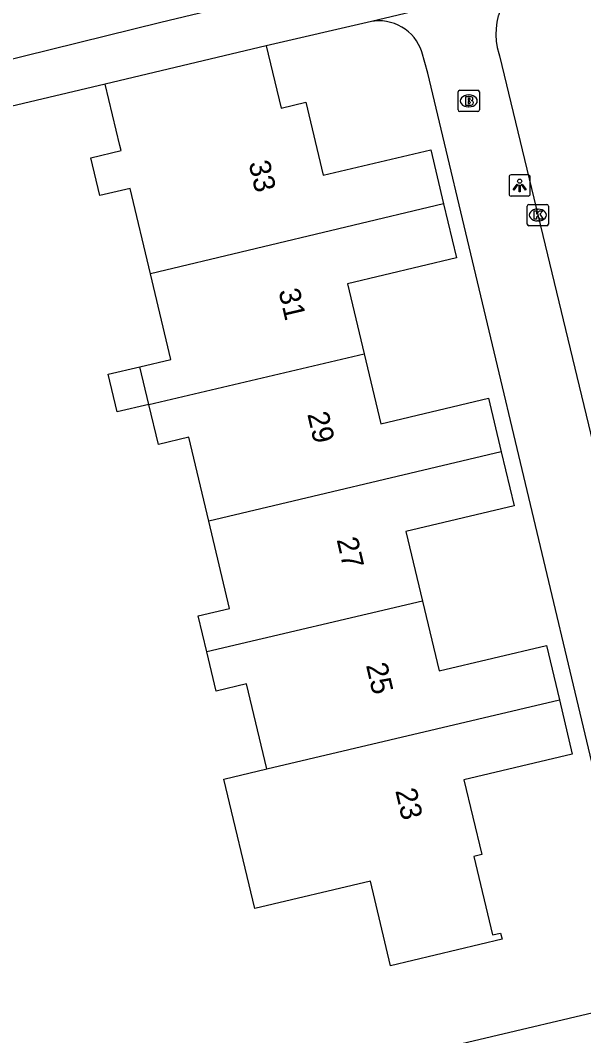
# Model space of a CAD drawing. Extents: x 158038 to 159242, y 380133 to 381214.
# Drawn here: x 158563.26 to 158589.79, y 380931.84 to 380979.68 of the extents above; entities that cross this region are included whole.
import ezdxf

# ---------------------------------------------------------------- set-up
doc = ezdxf.new("R2010")
doc.units = 0
for name, color, linetype in [('IMGEO_Brandkraan', 7, 'Continuous'), ('IMGEO_Fietspad_open', 7, 'Continuous'), ('IMGEO_Kolk', 7, 'Continuous'), ('IMGEO_Lichtpunt', 7, 'Continuous'), ('IMGEO_Pand', 7, 'Continuous'), ('IMGEO_Pand_nummerreeks', 7, 'Continuous'), ('IMGEO_Voetpad_open', 7, 'Continuous')]:
    doc.layers.add(name, color=color, linetype=linetype)

msp = doc.modelspace()

# ---------------------------------------------------------------- linework, layer by layer
at = {"layer": 'IMGEO_Brandkraan'}
for p, q in [((158583.878, 380975.455), (158583.878, 380976.307)), ((158583.953, 380976.381), (158584.805, 380976.381)), ((158584.366, 380976.161), (158584.391, 380976.161)), ((158584.879, 380976.307), (158584.879, 380975.455)), ((158584.805, 380975.381), (158583.953, 380975.381)), ((158584.389, 380975.601), (158584.364, 380975.601))]:
    msp.add_line(p, q, dxfattribs=at)
for points in [[(158583.878, 380975.455), (158583.878, 380976.307)], [(158583.953, 380976.381), (158584.805, 380976.381)], [(158584.879, 380976.307), (158584.879, 380975.455)], [(158584.226, 380976.081), (158584.226, 380975.681), (158584.439, 380975.681)], [(158584.457, 380976.081), (158584.226, 380976.081)], [(158584.405, 380976), (158584.351, 380976), (158584.351, 380975.924)], [(158584.351, 380975.924), (158584.404, 380975.924)], [(158584.413, 380975.848), (158584.351, 380975.848), (158584.351, 380975.767)], [(158584.351, 380975.767), (158584.413, 380975.767)], [(158584.805, 380975.381), (158583.953, 380975.381)]]:
    msp.add_lwpolyline(points, dxfattribs=at)
for centre, radius, start, end in [((158583.955, 380976.305), 0.0765, 91.552, 178.448), ((158583.955, 380976.305), 0.0765, 91.552, 178.448), ((158584.803, 380976.305), 0.0765, 1.552, 88.448), ((158584.803, 380976.305), 0.0765, 1.552, 88.448), ((158584.406, 380975.962), 0.0379, 267.8285, 90.9355), ((158584.414, 380975.807), 0.0404, 269.8759, 90.5077), ((158584.445, 380975.932), 0.251, 268.6676, 293.5347), ((158584.461, 380975.936), 0.145, 59.4692, 91.5367), ((158584.486, 380975.983), 0.0922, 285.5137, 58.1501), ((158584.491, 380975.791), 0.105, 301.3115, 78.989), ((158583.955, 380975.457), 0.0765, 181.552, 268.448), ((158583.955, 380975.457), 0.0765, 181.552, 268.448), ((158584.803, 380975.457), 0.0765, 271.552, 358.448), ((158584.803, 380975.457), 0.0765, 271.552, 358.448)]:
    msp.add_arc(centre, radius, start, end, dxfattribs=at)
for centre, major_axis, ratio, start_param, end_param in [((158584.365, 380975.881), (-0.387, 0.002), 0.722429, 4.712389, 7.853982), ((158584.39, 380975.881), (-0.39, 0.002), 0.717154, 1.570796, 4.712389)]:
    msp.add_ellipse(centre, major_axis=major_axis, ratio=ratio, start_param=start_param, end_param=end_param, dxfattribs=at)
at = {"layer": 'IMGEO_Fietspad_open'}
msp.add_lwpolyline([(158543.487, 380975.057), (158559.5, 380977.024), (158569.881, 380979.588), (158585.768, 380983.41), (158590.087, 380984.449), (158613.803, 380989.844), (158626.388, 380992.815), (158628.561, 380993.352), (158629.543, 380993.657), (158646.352, 380999.546)], dxfattribs=at)
at = {"layer": 'IMGEO_Kolk'}
for p, q in [((158587.13, 380970.077), (158587.13, 380970.929)), ((158587.205, 380971.003), (158588.057, 380971.003)), ((158588.131, 380970.929), (158588.131, 380970.077)), ((158587.618, 380970.783), (158587.643, 380970.783)), ((158588.057, 380970.003), (158587.205, 380970.003)), ((158587.641, 380970.223), (158587.616, 380970.223))]:
    msp.add_line(p, q, dxfattribs=at)
for points in [[(158587.13, 380970.077), (158587.13, 380970.929)], [(158587.205, 380971.003), (158588.057, 380971.003)], [(158588.131, 380970.929), (158588.131, 380970.077)], [(158587.451, 380970.703), (158587.574, 380970.703), (158587.574, 380970.552), (158587.704, 380970.703), (158587.868, 380970.703), (158587.722, 380970.552), (158587.875, 380970.303), (158587.723, 380970.303), (158587.638, 380970.467), (158587.574, 380970.4), (158587.574, 380970.303), (158587.451, 380970.303), (158587.451, 380970.703)], [(158588.057, 380970.003), (158587.205, 380970.003)]]:
    msp.add_lwpolyline(points, dxfattribs=at)
for centre, start, end in [((158587.207, 380970.927), 91.552, 178.448), ((158587.207, 380970.927), 91.552, 178.448), ((158588.055, 380970.927), 1.552, 88.448), ((158588.055, 380970.927), 1.552, 88.448), ((158587.207, 380970.079), 181.552, 268.448), ((158587.207, 380970.079), 181.552, 268.448), ((158588.055, 380970.079), 271.552, 358.448), ((158588.055, 380970.079), 271.552, 358.448)]:
    msp.add_arc(centre, 0.0765, start, end, dxfattribs=at)
for centre, major_axis, ratio, start_param, end_param in [((158587.617, 380970.503), (-0.387, 0.002), 0.722429, 4.712389, 7.853982), ((158587.642, 380970.503), (-0.39, 0.002), 0.717154, 1.570796, 4.712389)]:
    msp.add_ellipse(centre, major_axis=major_axis, ratio=ratio, start_param=start_param, end_param=end_param, dxfattribs=at)
at = {"layer": 'IMGEO_Lichtpunt'}
for p, q in [((158587.178, 380972.397), (158586.37, 380972.397)), ((158587.178, 380972.397), (158586.37, 380972.397)), ((158586.276, 380972.302), (158586.276, 380971.495)), ((158586.276, 380972.302), (158586.276, 380971.495)), ((158587.272, 380971.495), (158587.272, 380972.302)), ((158587.272, 380971.495), (158587.272, 380972.302)), ((158586.37, 380971.401), (158587.178, 380971.401)), ((158586.37, 380971.401), (158587.178, 380971.401))]:
    msp.add_line(p, q, dxfattribs=at)
for points in [[(158586.65, 380971.966), (158586.689, 380971.938), (158586.501, 380971.676), (158586.463, 380971.703), (158586.65, 380971.966)], [(158586.752, 380971.918), (158586.799, 380971.918), (158586.799, 380971.596), (158586.752, 380971.596), (158586.752, 380971.918)], [(158586.862, 380971.938), (158586.9, 380971.965), (158587.087, 380971.703), (158587.048, 380971.675), (158586.862, 380971.938)]]:
    msp.add_lwpolyline(points, dxfattribs=at)
msp.add_circle((158586.775, 380972.1), 0.0994, dxfattribs=at)
for centre, start, end in [((158586.37, 380972.302), 90, 180), ((158586.37, 380972.302), 90, 180), ((158587.178, 380972.302), 0, 90), ((158587.178, 380972.302), 0, 90), ((158586.37, 380971.495), 180, 270), ((158586.37, 380971.495), 180, 270), ((158587.178, 380971.495), 270, 0), ((158587.178, 380971.495), 270, 360)]:
    msp.add_arc(centre, 0.0946, start, end, dxfattribs=at)
at = {"layer": 'IMGEO_Pand'}
for points in [[(158574.841, 380978.474), (158567.252, 380976.671)], [(158574.841, 380978.474), (158575.536, 380975.545), (158576.705, 380975.818), (158577.522, 380972.378), (158582.586, 380973.583), (158583.191, 380971.038)], [(158569.385, 380967.739), (158568.429, 380971.758), (158567.007, 380971.42), (158566.584, 380973.2), (158568.005, 380973.538), (158567.949, 380973.773), (158567.252, 380976.671)], [(158583.191, 380971.038), (158569.385, 380967.739)], [(158583.191, 380971.038), (158583.797, 380968.491), (158578.665, 380967.27), (158579.452, 380963.963)], [(158568.89, 380963.356), (158570.345, 380963.702), (158569.385, 380967.739)], [(158569.313, 380961.578), (158579.452, 380963.963)], [(158579.452, 380963.963), (158580.234, 380960.673), (158585.306, 380961.879), (158585.908, 380959.349)], [(158569.313, 380961.578), (158567.813, 380961.225), (158567.391, 380962.999), (158568.89, 380963.356)], [(158569.313, 380961.578), (158568.89, 380963.356)], [(158572.131, 380956.083), (158571.19, 380960.039), (158569.76, 380959.699), (158569.313, 380961.578)], [(158585.908, 380959.349), (158572.131, 380956.083)], [(158585.908, 380959.349), (158586.514, 380956.802), (158581.42, 380955.59), (158582.201, 380952.308)], [(158572.04, 380949.918), (158571.635, 380951.62), (158573.109, 380951.97), (158572.131, 380956.083)], [(158582.201, 380952.308), (158572.04, 380949.918)], [(158582.201, 380952.308), (158582.983, 380949.021), (158588.036, 380950.223), (158588.647, 380947.654)], [(158574.868, 380944.403), (158573.914, 380948.415), (158572.478, 380948.073), (158572.04, 380949.918)], [(158588.647, 380947.654), (158589.253, 380945.105), (158584.15, 380943.891), (158584.988, 380940.367), (158584.618, 380940.279), (158585.498, 380936.582), (158585.877, 380936.672), (158585.947, 380936.381), (158580.693, 380935.131), (158579.744, 380939.12), (158574.296, 380937.823), (158572.845, 380943.926), (158574.868, 380944.403)], [(158574.868, 380944.403), (158588.647, 380947.654)]]:
    msp.add_lwpolyline(points, dxfattribs=at)
at = {"layer": 'IMGEO_Voetpad_open'}
for points in [[(158587.388, 380981.452), (158579.796, 380979.628)], [(158587.388, 380981.452), (158587.187, 380981.386), (158586.992, 380981.302), (158586.806, 380981.202), (158586.629, 380981.085), (158586.464, 380980.952), (158586.311, 380980.806), (158586.172, 380980.646), (158586.048, 380980.475), (158585.939, 380980.293), (158585.848, 380980.102), (158585.773, 380979.904), (158585.768, 380979.888), (158585.705, 380979.595), (158585.668, 380979.297), (158585.658, 380978.997), (158585.675, 380978.697), (158585.718, 380978.4), (158585.788, 380978.108), (158585.819, 380978.007), (158591.091, 380956.193)], [(158579.796, 380979.628), (158574.841, 380978.474)], [(158592.43, 380935.228), (158582.451, 380977.181), (158582.17, 380978.194), (158582.101, 380978.373), (158582.016, 380978.545), (158581.917, 380978.708), (158581.803, 380978.862), (158581.675, 380979.006), (158581.536, 380979.137), (158581.385, 380979.255), (158581.225, 380979.36), (158581.055, 380979.449), (158580.878, 380979.524), (158580.696, 380979.582), (158580.509, 380979.623), (158580.319, 380979.648), (158580.127, 380979.655), (158579.936, 380979.646), (158579.796, 380979.628)], [(158567.252, 380976.671), (158537.933, 380969.735)], [(158549.066, 380923.206), (158591.36, 380933.189)]]:
    msp.add_lwpolyline(points, dxfattribs=at)

# ---------------------------------------------------------------- texts
at = {"layer": 'IMGEO_Pand_nummerreeks'}
for s, p in [('33', (158574.005, 380972.956)), ('31', (158575.412, 380966.93)), ('29', (158576.769, 380961.127)), ('27', (158578.151, 380955.212)), ('25', (158579.533, 380949.298)), ('23', (158580.915, 380943.383))]:
    msp.add_text(s, height=1, rotation=283.1519, dxfattribs=at).set_placement(p)

doc.saveas('drawing.dxf')
